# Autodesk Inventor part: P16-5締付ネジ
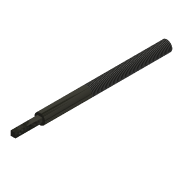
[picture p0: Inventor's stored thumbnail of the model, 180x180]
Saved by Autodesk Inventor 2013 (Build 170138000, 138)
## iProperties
Created: 2008-07
Part Number: P16-5締付ネジ
Document SubType Name: Modeling
Designer: y-shimohigashi
Density: 1 g/cm^3
Material: 一般
Author: y-shimohigashi
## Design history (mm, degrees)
sketch "スケッチ2"
  geometry: C1 r 8 at (0, 0); 1 further point
  constraints: 1 centre point, 1 coincident
  dimensions: "d0" = 16 diameter of C1
extrude "押し出し1" new body sketch "スケッチ2" distance "d1" = 190; taper "d2" = 0 deg
sketch "スケッチ3"
  geometry: L1 (3.536, 3.536)-(-3.536, 3.536); L2 (-3.536, 3.536)-(-3.536, -3.536); L3 (-3.536, -3.536)-(3.536, -3.536); L4 (3.536, -3.536)-(3.536, 3.536); L5 (-3.536, 3.536)-(3.536, -3.536); 2 further points
  constraints: 10 end point, 2 parallel, 2 perpendicular, 1 coincident, 1 horizontal, 1 midpoint
  dimensions: "d3" = 10 distance of L1.end L3.end
extrude "押し出し2" join sketch "スケッチ3" distance "d4" = 40; taper "d5" = 0 deg
sketch "スケッチ4"
  geometry: L1 (-86, 0)-(236, 0) reference; L2 (-40, -3.536)-(-40, 3.536) reference; 1 further point
  constraints: 1 point on line
  dimensions: "d6" = 7 distance from line of point (-33, 0) L2
hole "穴1" sketch "スケッチ4" diameter "d7" = 2.459; stored, may be unused: countersink angle "d11" = 90 deg, drill point angle "d13" = 118 deg; dims "d8" = 6, "d9" = 4, "d10" = 2, "d12" = 8
hole "穴2" sketch "スケッチ4" diameter "d14" = 2.459; stored, may be unused: countersink angle "d18" = 90 deg, drill point angle "d20" = 118 deg; dims "d15" = 6, "d16" = 4, "d17" = 2, "d19" = 8
feature "ねじ1" dims "d21" = 120, "d22" = 0
node "ソリッド1"
node "ソリッド ボディ"
node "サーフェス ボディ"
